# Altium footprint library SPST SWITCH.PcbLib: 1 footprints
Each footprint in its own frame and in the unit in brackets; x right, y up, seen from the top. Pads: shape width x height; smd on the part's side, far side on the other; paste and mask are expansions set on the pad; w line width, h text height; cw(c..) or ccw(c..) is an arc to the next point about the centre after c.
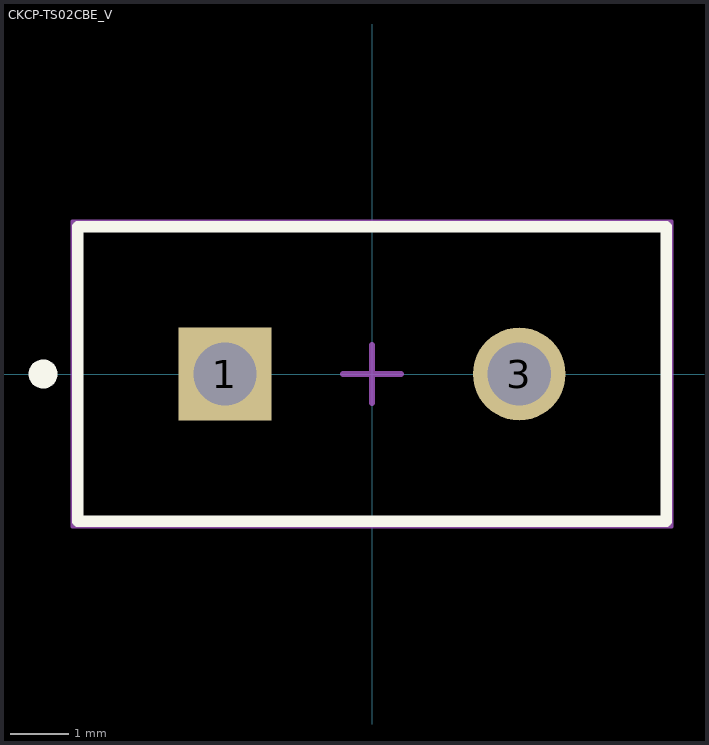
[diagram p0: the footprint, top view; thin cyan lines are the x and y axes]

## CKCP-TS02CBE_V [mm] "THD, 2-Leads, Body 10.16x5.08mm"
height 12.91
pads (2):
  rect 1.6x1.6 hole 1.09: 1(-2.54,0)
  round 1.6 hole 1.09: 3(2.54,0)
Top Overlay:
  circle w0.25: c-5.68,0 r0.125
  lines w0.2: -5.08,-2.54 5.08,-2.54 5.08,2.54 -5.08,2.54 -5.08,-2.54
Mechanical 13:
  lines w0.1: -5.08,-2.54 -5.08,2.54 5.08,2.54 5.08,-2.54 -5.08,-2.54
Mechanical 15:
  lines w0.05: -5.18,-2.64 5.18,-2.64 5.18,2.64 -5.18,2.64 -5.18,-2.64
  lines w0.1: -0.5,0 0.5,0 ; 0,-0.5 0,0.5
3D body "ts02c.stp": height 12.93, standoff -3.27, extent -5.08,-2.54 5.08,2.54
